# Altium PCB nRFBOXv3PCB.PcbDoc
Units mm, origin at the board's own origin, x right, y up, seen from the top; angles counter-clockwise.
Board outline 47.75 x 87.5 mm, 2 copper layers (Top Layer, Bottom Layer); 76 components, 63 nets, 357 pads, 84 vias.
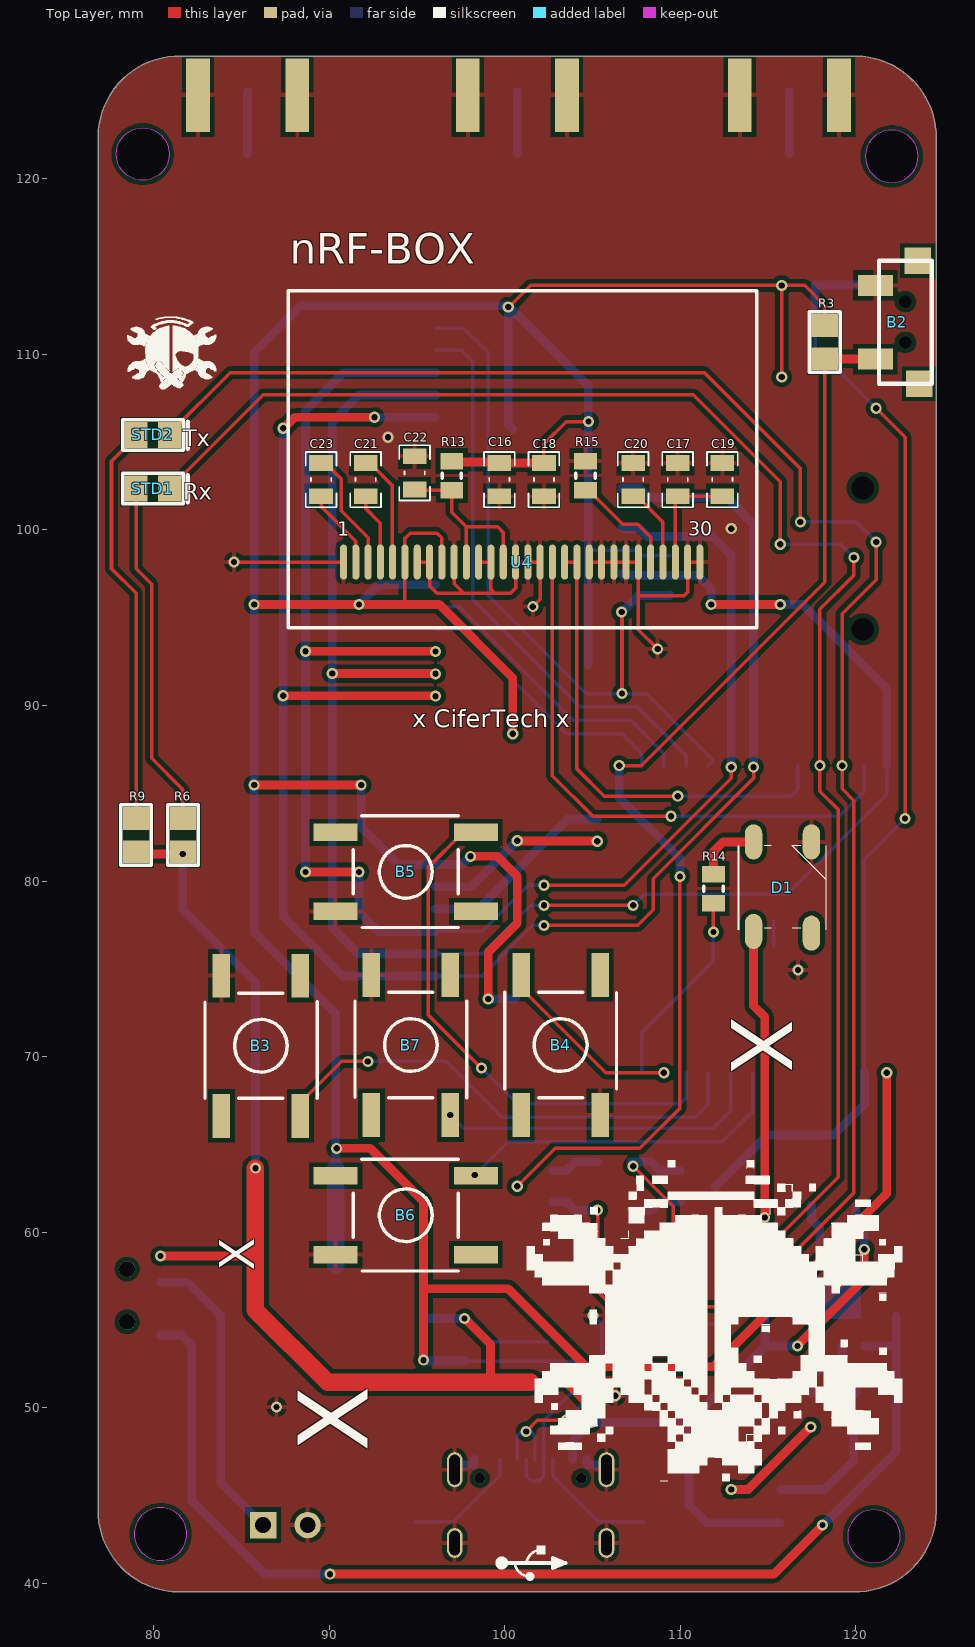
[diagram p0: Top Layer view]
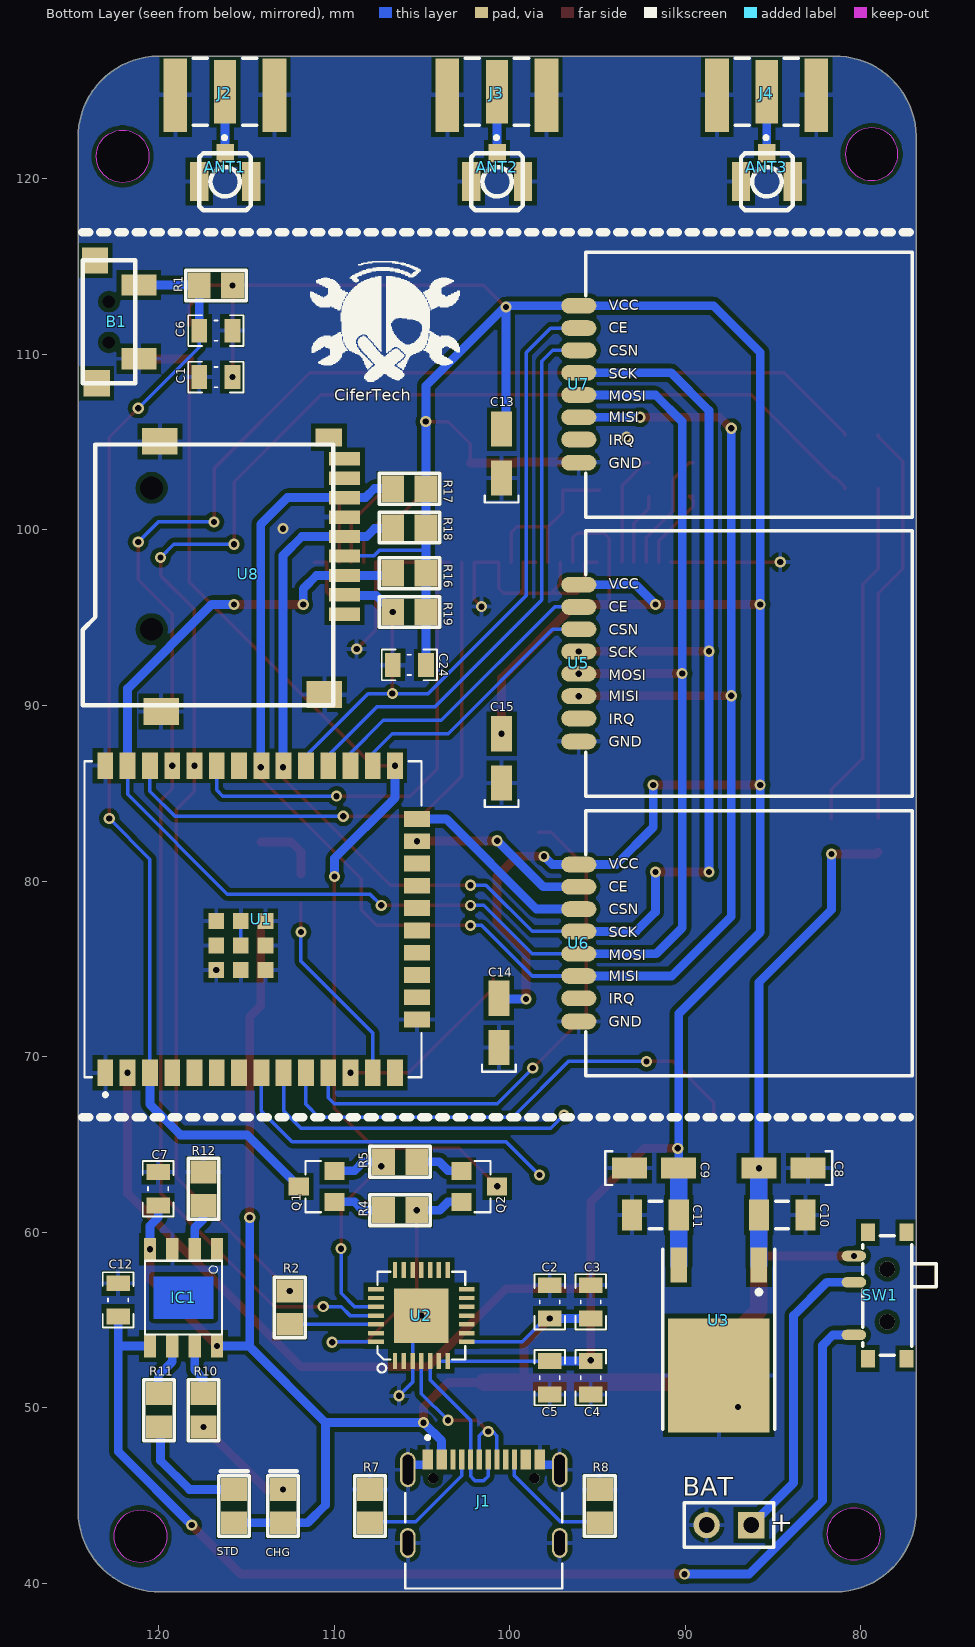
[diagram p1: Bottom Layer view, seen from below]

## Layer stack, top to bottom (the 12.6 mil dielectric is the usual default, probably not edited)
Top Solder: solder mask 0.0102, Solder Resist, Dk 3.5
Top Layer: signal copper 0.0356
Dielectric 1: dielectric 0.32, FR-4, Dk 4.8
Bottom Layer: signal copper 0.0356
Bottom Solder: solder mask 0.0102, Solder Resist, Dk 3.5

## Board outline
76.835,44.196 ccw(c81.47,44.133) 81.407,39.497 119.888,39.497 ccw(c119.951,44.132) 124.587,44.069 124.587,122.301 ccw(c119.952,122.364) 120.015,127 81.534,127 ccw(c81.471,122.365) 76.835,122.428
cut-out: 78.891,42.799 ccw(c80.391,42.799) 80.391,41.299 ccw(c80.391,42.799) 81.891,42.799 ccw(c80.391,42.799) 80.391,44.299 ccw(c80.391,42.799)
cut-out: 119.531,42.672 ccw(c121.031,42.672) 121.031,41.172 ccw(c121.031,42.672) 122.531,42.672 ccw(c121.031,42.672) 121.031,44.172 ccw(c121.031,42.672)
cut-out: 79.375,119.912 cw(c79.375,121.412) 77.875,121.412 cw(c79.375,121.412) 79.375,122.912 cw(c79.375,121.412) 80.875,121.412 cw(c79.375,121.412)
cut-out: 120.547,121.285 ccw(c122.047,121.285) 122.047,119.785 ccw(c122.047,121.285) 123.547,121.285 ccw(c122.047,121.285) 122.047,122.785 ccw(c122.047,121.285)

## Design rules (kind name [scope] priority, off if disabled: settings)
Clearance [All] p1: gap=0.254 ignorepadtopadclearanceinfootprint=FALSE except(0: Arc-Hole Track-Hole SMDPad-Hole THPad-Hole Via-Hole Fill-Hole Poly-Hole Region-Hole Text-Hole)
PolygonConnect [All] p1: connectstyle=Relief reliefconductorwidth=0.254 reliefentries=4 polygonreliefangle="90 Angle" airgapwidth=0.254
RoutingVias [All] p1: holewidth=0.711 width=1.27 viastyle="Through Hole" minholewidth=0.711 minwidth=1.27 maxholewidth=0.711 maxwidth=1.27
SolderMaskExpansion [All] p1: expansion=0.102
Width [All] p1: maxlimit=1 minlimit=0.2 preferedwidth=0.5 minimp=50.000000 maximp=50.000000 favimp=50.000000
30 further rules are at their usual default settings.

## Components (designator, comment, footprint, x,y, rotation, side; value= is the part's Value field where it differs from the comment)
ANT1 "ANT U.FL" "U.FL SMD" 116.205,120.65 r0 bottom
ANT2 "ANT U.FL" "U.FL SMD" 100.711,120.65 r0 bottom
ANT3 "ANT U.FL" "U.FL SMD" 85.344,120.65 r0 bottom
B1 "BUTTON" "PUSH BUTTON SMD" 122.809,111.76 r0 bottom
B2 "BUTTON" "PUSH BUTTON SMD" 122.809,111.926 r0 top
B3 "Button" "PUSH BUTTON 4 PIN SMD 5" 86.106,70.612 r90 top locked
B4 "Button" "PUSH BUTTON 4 PIN SMD 5" 103.187,70.657 r270 top locked
B5 "Button" "PUSH BUTTON 4 PIN SMD 5" 94.361,80.522 r180 top locked
B6 "Button" "PUSH BUTTON 4 PIN SMD 5" 94.361,60.96 r180 top locked
B7 "Button" "PUSH BUTTON 4 PIN SMD 5" 94.647,70.657 r90 top locked
BAT "Battery" Bat 69.342,52.959 r0 bottom
C1 "100nf" CAP0805 116.73,108.712 r180 bottom
C2 "10uf" CAP0805 97.714,56.023 r270 bottom
C3 "100nf" CAP0805 95.377,56.023 r270 bottom
C4 "10uf" CAP0805 95.377,51.705 r90 bottom
C5 "100nf" CAP0805 97.714,51.705 r90 bottom
C6 "100nf" CAP0805 116.73,111.351 r0 bottom
C7 "100nf" CAP0805 120.025,62.468 r270 bottom
C8 "Capacitor Tantalum SMD" "Tan 1206 (3216X18L) Size A" 77.665,69.103 r0 bottom value=2.2uf
C9 "Capacitor Tantalum SMD" "Tan 1206 (3216X18L) Size A" 98.502,58.181 r180 bottom value=2.2uf
C10 "10uf" "CAP 1206 (3216X15L)" 84.474,60.974 r0 bottom
C11 "10uf" "CAP 1206 (3216X15L)" 91.694,60.974 r180 bottom
C12 "100nf" CAP0805 122.301,56.134 r270 bottom
C13 "Capacitor Tantalum SMD" "Tan 1206 (3216X18L) Size A" 94.996,97.615 r90 bottom value=10uf
C14 "Capacitor Tantalum SMD" "Tan 1206 (3216X18L) Size A" 95.154,65.185 r90 bottom value=10uf
C15 "Capacitor Tantalum SMD" "Tan 1206 (3216X18L) Size A" 94.996,80.258 r90 bottom value=10uf
C16 "10uf" CAP0805 99.695,102.87 r270 top
C17 "10uf" CAP0805 109.855,102.87 r270 top
C18 "100nf" CAP0805 102.235,102.87 r270 top
C19 "100nf" CAP0805 112.395,102.87 r270 top
C20 "2.2uf" CAP0805 107.315,102.87 r90 top
C21 "1uf" CAP0805 92.075,102.87 r90 top
C22 "2.2uf" CAP0805 94.869,103.251 r90 top
C23 "1uf" CAP0805 89.535,102.87 r90 top
C24 "100nf" CAP0805 105.711,92.311 r0 bottom
CHG "LED" L0805 112.903,45.339 r90 bottom
D1 "LED RGB WS2812" "LED 5050 WS2812B" 115.824,79.629 r90 top
IC1 "TP4056" SOP-8 118.578,56.266 r270 bottom
J1 "TYPE-C-31-M-12" HRO_TYPE-C-31-M-12 101.473,42.291 r180 bottom
J2 "SMA" SAMTEC_SMA-J-P-H-ST-EM1 116.216,124.968 r0 bottom
J3 "SMA" SAMTEC_SMA-J-P-H-ST-EM1 100.722,124.968 r0 bottom
J4 "SMA" SAMTEC_SMA-J-P-H-ST-EM1 85.355,124.968 r0 bottom
Q1 "S8050" SOT-23 110.998,62.596 r90 bottom
Q2 "S8050" SOT-23 101.727,62.596 r270 bottom
R1 "4.7k" "RES 0805" 117.68,113.931 r270 bottom
R2 "470" "RES 0805" 112.522,56.645 r0 bottom
R3 "4.7k" "RES 0805" 118.237,109.755 r0 top
R4 "12k" "RES 0805" 105.288,61.25 r90 bottom
R5 "12k" "RES 0805" 107.188,64.008 r270 bottom
R6 "1k" "RES 0805" 81.666,81.661 r0 top
R7 "5.1k" "RES 0805" 107.95,43.439 r180 bottom
R8 "5.1k" "RES 0805" 94.869,43.439 r180 bottom
R9 "1k" "RES 0805" 78.999,81.666 r0 top
R10 "1k" "RES 0805" 117.435,50.8 r0 bottom
R11 "1k" "RES 0805" 119.975,50.8 r0 bottom
R12 "1k" "RES 0805" 117.435,61.518 r180 bottom
R13 "10k" "RES 0805 (2012X06L)" 96.982,102.268 r90 top
R14 "1k" "RES 0805 (2012X06L)" 111.887,78.741 r90 top
R15 "390k" "RES 0805 (2012X06L)" 104.602,102.268 r90 top
R16 "10K" "RES 0805" 106.661,97.536 r270 bottom
R17 "10K" "RES 0805" 106.661,102.349 r270 bottom
R18 "10K" "RES 0805" 106.661,100.133 r270 bottom
R19 "10K" "RES 0805" 106.661,95.32 r270 bottom
STD "LED" L0805 115.697,45.339 r90 bottom
STD1 "LED" L0805 80.899,102.362 r0 top
STD2 "LED" L0805 80.899,105.41 r0 top
SW1 "SlideSwitch" SWSLIDT_SPDT_MSS3 78.486,56.388 r270 bottom
U1 "ESP32-WROOM-32U" XCVR_ESP32-WROOM-32U 114.623,77.824 r90 bottom
U2 "CP2102" QFN28G_0.5-5X5MM 105.029,55.245 r90 bottom
U3 "LF33" D-PACK 85.799,58.13 r0 bottom
U4 "OLED_0.96IN_WHITE" OLED_0.96IN_WHITE_SSD1306 100.965,98.171 r0 top locked
U5 "NRF24L01" NRF24L01_GT24MINI_MS 86.36,92.443 r180 bottom
U6 "NRF24L01" NRF24L01_GT24MINI_MS 86.36,76.499 r180 bottom
U7 "NRF24L01" NRF24L01_GT24MINI_MS 86.36,108.331 r180 bottom
U8 "SD CARD SPI MODE" "MICRO SD" 110.046,104.868 r270 bottom
? "Comment" "LOGO USB1" 101.473,41.148 r0 top

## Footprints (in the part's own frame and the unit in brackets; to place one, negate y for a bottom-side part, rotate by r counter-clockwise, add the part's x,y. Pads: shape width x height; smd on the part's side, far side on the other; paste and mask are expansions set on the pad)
Bat [mm]
  rect 1.5x1.5 hole 0.9: 1(16.891,9.652)
  round 1.5 hole 0.9: 2(19.431,9.652)
  silkscreen extent 15.62,8.38 20.7,10.92
CAP0805 [mm] "Chip Capacitor, 2-Leads, Body 2/00x1/25mm, IPC Medium Density DESIGNER:ABBAS BASEREH"
  rect 0.9x1.35 smd: 1(-0.95,0) 2(0.95,0)
  silkscreen extent -1.58,-0.87 1.58,0.87, body extent -1.02,-0.65 1.02,0.65, height 0.5
"CAP 1206 (3216X15L)" [mm] "Chip Capacitor, 2-Leads, Body 3.2x1.6mm, IPC High Density"
  rect 1.15x1.75 smd: 1(-1.325,0) 2(1.325,0)
  silkscreen extent -0.35,-0.77 0.35,0.77, body extent -1.6,-0.8 1.6,0.8, height 1
D-PACK [mm] "D-PACK"
  rect 0.95x2 smd: 1(0,0) 3(4.57,0)
  rect 5.8x6.5 smd: 2(2.285,6.3)
  silkscreen extent -0.91,-0.9 5.49,9.35, body extent -1.03,-0.45 5.55,9.25, height 2.3
HRO_TYPE-C-31-M-12 [mm]
  rect 0.6x1.14 smd mask+0.05: A1_B12(-3.2,4.75) A4_B9(-2.4,4.75) B1_A12(3.2,4.75) B4_A9(2.4,4.75)
  rect 0.3x1.14 smd mask+0.05: A5(-1.25,4.75) A6(-0.25,4.75) A7(0.25,4.75) A8(1.25,4.75) B5(1.75,4.75) B6(0.75,4.75) B7(-0.75,4.75) B8(-1.75,4.75)
  oval 0.9x2 hole 0.6 slot 1.7 at 90 deg: S1(-4.325,4.17) S2(4.325,4.17)
  oval 0.9x1.7 hole 0.6 slot 1.4 at 90 deg: S3(-4.325,0) S4(4.325,0)
  round 0.6 hole 0.6 unplated: ""(-2.89,3.68) ""(2.89,3.68)
  silkscreen extent -4.47,-2.6 4.47,6.1, body extent -4.47,-2.6 4.47,5.3, height 3.31
L0805 [mm] "Body 2.0x1.3mm, IPC High Density"
  rect 1.3x1.5 smd: A(-1.9,0) K(0,0)
  silkscreen extent -2.68,-0.87 1.03,0.87, body extent -1.95,-0.63 0.05,0.62, height 0.68
"LED 5050 WS2812B" [mm]
  oval 2x1 smd: 1(-2.5,1.65) 2(-2.6,-1.65) 3(2.6,-1.65) 4(2.6,1.65)
  silkscreen extent -2.41,-2.49 2.4,2.51, body extent -2.74,-2.49 2.66,2.51, height 1.6
"LOGO USB1" [mm] "General USB Logo"
  silkscreen extent -1.82,-0.89 2.01,0.99
"MICRO SD" [mil] "MICRO SD"
  rect 30x70 smd: 1(380.91,25.07) 2(337.29,25.07) 3(293.66,25.07) 4(250.04,25.07) 5(206.41,25.07) 6(162.79,25.07) 7(119.16,25.07) 8(75.54,25.07) 9(31.91,25.07)
  rect 60x80 smd: 6(-7.09,-388.93) 6(560.91,-19.93) 6(598.91,-385.93)
  rect 40x60 smd: 10(-16.09,-9.93)
  round 0 hole 51.18: ""(97.44,-407.48) ""(414.37,-407.48)
  silkscreen extent 0,-562 585,0, body extent -25,-565 609,26, height 73
NRF24L01_GT24MINI_MS [mm] "2.4GHz Transceiver MODULE, SMD"
  oval 2x0.9 smd mask+0.1: 1(-9.7,4.44) 2(-9.7,3.17) 3(-9.7,1.9) 4(-9.7,0.63) 5(-9.7,-0.64) 6(-9.7,-1.91) 7(-9.7,-3.18) 8(-9.7,-4.5)
  silkscreen extent -9.3,-7.6 9.3,7.5, body extent -9.2,-7.5 9.2,7.4, height 2.25
OLED_0.96IN_WHITE_SSD1306 [mm] "OLED, 0.96IN, Monochrome white, SSD1306"
  oval 0.4x2 smd: 1(-10.15,0) 2(-9.45,0) 3(-8.75,0) 4(-8.05,0) 5(-7.35,0) 6(-6.65,0) 7(-5.95,0) 8(-5.25,0) 9(-4.55,0) 10(-3.85,0) 11(-3.15,0) 12(-2.45,0) 13(-1.75,0) 14(-1.05,0) 15(-0.35,0) 16(0.35,0) 17(1.05,0) 18(1.75,0) 19(2.45,0) 20(3.15,0) 21(3.85,0) 22(4.55,0) 23(5.25,0) 24(5.95,0) 25(6.65,0) 26(7.35,0) 27(8.05,0) 28(8.75,0) 29(9.45,0) 30(10.15,0)
  silkscreen extent -13.3,-3.75 13.4,15.45, body extent -13.35,-6.82 13.35,15.4, height 3.82
"PUSH BUTTON 4 PIN SMD 5" [mm]
  rect 2.5x1 smd: 1(-3.992,2.25) 2(-3.992,-2.25) 3(3.992,-2.25) 4(3.992,2.25)
  silkscreen extent -3,-3.2 3,3.17, body extent -4.5,-3 4.5,3, height 5
"PUSH BUTTON SMD" [mm]
  rect 1.5x1.5 smd: 1(0.712,3.405) 4(0.812,-3.595)
  rect 2x1.2 smd: 2(-1.688,2.005) 3(-1.688,-2.195)
  round 0 hole 0.7: ""(0.012,-1.245) ""(0.02,1.079)
  silkscreen extent -1.49,-3.59 1.51,3.41
QFN28G_0.5-5X5MM [mm]
  rect 0.9x0.254 smd: 1(-2.59,1.5) 2(-2.59,1) 3(-2.59,0.5) 4(-2.59,0) 5(-2.59,-0.5) 6(-2.59,-1) 7(-2.59,-1.5) 15(2.59,-1.5) 16(2.59,-1) 17(2.59,-0.5) 18(2.59,0) 19(2.59,0.5) 20(2.59,1) 21(2.59,1.5)
  rect 0.254x0.9 smd: 8(-1.5,-2.59) 9(-1,-2.59) 10(-0.5,-2.59) 11(0,-2.59) 12(0.5,-2.59) 13(1,-2.59) 14(1.5,-2.59) 22(1.5,2.59) 23(1,2.59) 24(0.5,2.59) 25(0,2.59) 26(-0.5,2.59) 27(-1,2.59) 28(-1.5,2.59)
  rect 3.1x3.1 smd paste-3: 29(0,0)
  silkscreen extent -3.25,-2.5 2.5,2.5
"RES 0805" [mm] "RES 0805"
  rect 1.5x1.3 smd: 1(0,0) 2(0,1.9)
  silkscreen extent -0.87,-0.77 0.87,2.68, body extent -0.63,-0.07 0.64,1.97, height 0.6
"RES 0805 (2012X06L)" [mm] "Chip Resistor, 2-Leads, Body 2.0x1.3mm, IPC High Density _ (0.100 W)"
  rect 0.95x1.3 smd: 1(0,0) 2(1.65,0)
  silkscreen extent 0.67,-0.55 0.97,0.55, body extent -0.19,-0.63 1.84,0.64, height 0.6
SAMTEC_SMA-J-P-H-ST-EM1 [mm]
  rect 1.27x3.6 smd: 1(0,0)
  rect 1.35x4.2 smd: 2_1(-2.825,0.2) 3_1(2.825,0.2)
  rect 1.35x4.2 smd far side: 2_2(-2.825,0.2) 3_2(2.825,0.2)
  silkscreen extent -1.8,-1.9 1.8,2.72, body extent -3.17,-11.42 3.18,1.91, height 3.55
SOP-8 [mm]
  rect 1.3x0.7 smd: 1(-2.75,1.905) 2(-2.75,0.635) 3(-2.75,-0.635) 4(-2.75,-1.905) 5(2.75,-1.905) 6(2.75,-0.635) 7(2.75,0.635) 8(2.75,1.905)
  Top Layer region: 1.2,-1.7 -1.2,-1.7 -1.2,1.7 1.2,1.7
  silkscreen extent -2.1,-2.2 2.1,2.2
SOT-23 [mil]
  rect 40x45 smd: 1(-35,-40) 2(35,-40) 3(0,40)
  silkscreen extent -58,-10 58,25, body extent -57,-51 57,51, height 55
SWSLIDT_SPDT_MSS3 [mm] "Switch, Slide, SPDT,"
  oval 0.6x1.4 smd: 1(2.25,-1.9) 2(-0.75,-1.9) 3(-2.25,-1.9)
  rect 1x0.8 smd: EP(-3.6,-1.1) EP(-3.6,1.1) EP(3.6,-1.1) EP(3.6,1.1)
  round 0.9 hole 0.9 unplated: ""(-1.5,0) ""(1.5,0)
  silkscreen extent -3.4,-1.4 3.4,2.8, body extent -3.85,-2.24 3.85,2.76, height 1.4
"Tan 1206 (3216X18L) Size A" [mil]
  rect 78.7x47.2 smd: 1(210,215) 2(320.22,215)
  silkscreen extent 156,177 171,253, body extent 193,179 336,250, height 71
"U.FL SMD" [mm] "U.FL Antenna-Design:Ali Hafizi"
  rect 1x1.05 smd: 1(0.002,-0.8)
  rect 1.05x2.2 smd: 2(-1.475,0.8) 2(1.475,0.8)
  silkscreen extent -1.47,-0.8 1.47,2.44, body extent -1.73,-0.76 1.67,2.34, height 1.25
XCVR_ESP32-WROOM-32U [mm]
  rect 1.5x0.9 smd: 1(-8.75,8.41) 2(-8.75,7.14) 3(-8.75,5.87) 4(-8.75,4.6) 5(-8.75,3.33) 6(-8.75,2.06) 7(-8.75,0.79) 8(-8.75,-0.48) 9(-8.75,-1.75) 10(-8.75,-3.02) 11(-8.75,-4.29) 12(-8.75,-5.56) 13(-8.75,-6.83) 14(-8.75,-8.1) 25(8.75,-8.1) 26(8.75,-6.83) 27(8.75,-5.56) 28(8.75,-4.29) 29(8.75,-3.02) 30(8.75,-1.75) 31(8.75,-0.48) 32(8.75,0.79) 33(8.75,2.06) 34(8.75,3.33) 35(8.75,4.6) 36(8.75,5.87) 37(8.75,7.14) 38(8.75,8.41)
  rect 0.9x1.5 smd: 15(-5.715,-9.35) 16(-4.445,-9.35) 17(-3.175,-9.35) 18(-1.905,-9.35) 19(-0.635,-9.35) 20(0.635,-9.35) 21(1.905,-9.35) 22(3.175,-9.35) 23(4.445,-9.35) 24(5.715,-9.35)
  rect 0.9x0.9 smd: 39_1(-2.9,2.09) 39_2(-1.5,2.09) 39_3(-0.1,2.09) 39_4(-2.9,0.69) 39_5(-1.5,0.69) 39_6(-0.1,0.69) 39_7(-2.9,-0.71) 39_8(-1.5,-0.71) 39_9(-0.1,-0.71)
  round 0 all layers, no hole mask+0: 40_1(-2.2,2.09) 40_2(-0.8,2.09) 40_3(-2.9,1.39) 40_4(-1.5,1.39) 40_5(-0.1,1.39) 40_6(-2.2,0.69) 40_7(-0.8,0.69) 40_8(-2.9,-0.01) 40_9(-1.5,-0.01) 40_10(-0.1,-0.01) 40_11(-2.2,-0.71) 40_12(-0.8,-0.71)
  silkscreen extent -10.1,-9.6 9,9.6, body extent -9,-9.6 9,9.6, height 3.35

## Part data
ANT1 ANT2 ANT3: "Antenna"
B1 B2: library part "PUSH BUTTON RIGHT", "PUSH BUTTON"
B3 B4 B5 B6 B7: library part "PUSH BUTTON 4 PIN", "PUSH BUTTON"
C1 C2 C3 C4 C5 C6 C7 C10 C11 C12 C16 C17 C18 C19 C20 C21 C22 C23 C24: library part "CAP SMD", "Capacitor"
D1: "LED"
IC1: "Complete single cell Li-Ion battery with a constant current / constant voltage linear charger", Package="Package Analog Devices"
J1: "USB Connectors 24 Receptacle 1 8.94*7.3mm RoHS", Package=Package
J2 J3 J4: library part SMA-J-P-H-ST-EM1, "SMA Connector Jack, Female Socket 50Ohm Board Edge, End Launch Solder", Package=None
Q1 Q2: library part SMD-TRANSISTORS-NPN-25V-500MW(SOT-23), "Bipolar (BJT) Transistor NPN 25 V 500 mA 150MHz 300 mW Surface Mount SOT-23", Package=None
R1 R2 R3 R4 R5 R6 R7 R8 R9 R10 R11 R12 R13 R14 R15 R16 R17 R18 R19: library part RES, "RESISTOR"
SW1: library part SWSLIDT_SPDT_MSS3, "SWITCH, SLIDE, SPDT, SMD"
U1: "Bluetooth, WiFi 802.11b/g/n, Bluetooth v4.2 +EDR, Class 1, 2 and 3 Transceiver Module 2.4GHz ~ 2.5GHz Antenna Not Included, U.FL Surface Mount", Package="NON STANDARD-39 Espressif"
U2: library part INTERFACE-CP2102-GMR(QFN28), "USB Bridge, USB to UART USB 2.0 UART Interface 28-QFN _5x5_", Package="VFQFN-28 Vishay Siliconix"
U3: "3.3V VOLTAGE REGULATOR"
U4: library part OLED_0.96IN_WHITE_SSD1306, "OLED, 0.96\", Monochrome white, SSD1306"
U5 U6 U7: library part NRF24L01_GT24MINI_MS, "2.4GHz Transceiver MODULE, SMD"

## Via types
v1: diameter 0.635, hole 0.356, Top Layer to Bottom Layer, 84 vias

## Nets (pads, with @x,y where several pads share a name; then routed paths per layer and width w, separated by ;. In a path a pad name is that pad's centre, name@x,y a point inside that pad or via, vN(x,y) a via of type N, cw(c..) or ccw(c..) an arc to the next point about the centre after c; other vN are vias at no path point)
3v3: C1.2 C4.2 C5.2 C9.2 C11.2 C13.2 C14.2 C15.2 C16.1 C18.1 C24.1 R1.2 R3.2 R13.2 R16.2 R17.2 R18.2 R19.2 U1.2 U2.6 U2.7 U3.3 U4.6 U4.9 U5.1 U6.1 U7.1 U8.4 | length 261.8
  Top Layer w0.2: 94.315,95.758 U4.6 94.315,99.522 94.615,99.822 96.139,99.822 96.415,99.546 U4.9 ; v1(100.203,112.709) 100.265,112.709 101.487,113.931 v1(115.78,113.931) ; C18.1 102.235,104.902 103.505,106.172 v1(104.775,106.172) ; v1(115.78,108.712) v1(115.78,113.931) ; R3.2 118.237,112.776 117.082,113.931 v1(115.78,113.931)
  Top Layer w0.5: v1(85.725,85.471) v1(91.821,85.471) ; v1(85.725,95.758) v1(91.694,95.758) 94.315,95.758 96.266,95.758 100.457,91.567 v1(100.457,88.392) ; v1(90.424,64.77) 92.329,64.77 95.377,61.722 95.377,56.769 ; v1(95.377,52.705) 95.377,56.769 ; R13.2 97.031,103.869 99.646,103.869 C16.1 C18.1 ; v1(98.044,81.407) 99.568,81.407 100.711,80.264 100.711,77.597 99.06,75.946 v1(99.06,73.279) ; v1(121.763,69.074) 121.763,62.2 111.887,52.324 104.648,52.324 100.203,56.769 95.377,56.769
  Bottom Layer w0.2: C5.2 U2.7 U2.6 ; 104.761,98.835 107.413,98.835 107.731,98.517 U8.4
  Bottom Layer w0.5: C9.2 90.369,72.445 85.725,77.089 v1(85.725,85.471) v1(85.725,95.758) 85.725,110.109 88.387,112.771 U7.1 v1@100.203,112.771 ; v1(91.694,95.758) 92.819,96.883 U5.1 ; v1(91.821,85.471) 91.821,83.058 93.94,80.939 U6.1 97.576,80.939 v1(98.044,81.407) ; C4.2 C5.2 ; v1(99.06,73.279) 100.575,73.279 C14.2 ; C13.2 100.203,106.003 v1(100.203,112.709) v1@100.203,112.771 ; C24.1 104.761,95.32 R16.2 104.761,98.835 R18.2 R17.2 104.761,108.218 100.208,112.771 v1@100.203,112.771
  Bottom Layer w1: U3.3 C11.2 C9.2
+5v: C2.2 C3.2 C7.2 C8.2 C10.2 CHG.A D1.1 IC1.4 IC1.8 J1.A4_B9 R6.1 R9.1 STD.A SW1.3 U2.8 U3.1 | length 135.6
  Top Layer w0.5: R9.1 79.131,81.534 v1(81.661,81.534) ; v1(80.386,58.638) 85.763,58.638 85.798,58.674 ; v1(97.714,55.073) 99.187,53.6 99.187,51.435 ; 101.473,51.435 103.505,51.435 104.902,50.038 v1(104.902,49.144) ; D1.1 114.174,72.897 114.808,72.263 v1(114.808,60.833) ; v1(116.673,53.516) 120.483,57.326 v1(120.483,59.016)
  Top Layer w1: v1(85.798,63.642) 85.798,58.674 85.798,55.553 89.916,51.435 99.187,51.435 101.473,51.435
  Bottom Layer w0.2: v1(97.714,55.073) 97.962,55.073 99.29,53.745 U2.8
  Bottom Layer w0.5: v1(81.661,81.534) 81.661,78.359 85.798,74.222 v1(85.798,63.642) ; C3.2 v1(97.714,55.073) ; J1.A4_B9 103.873,48.115 v1(104.902,49.144) 110.49,49.144 ; v1(114.808,60.833) 114.808,53.57 114.862,53.516 ; STD.A CHG.A 111.501,43.439 110.49,44.45 110.49,49.144 ; v1(116.673,53.516) 114.862,53.516 ; C7.2 120.015,61.508 120.015,60.833 120.483,60.365 v1(120.483,59.016) ; 110.49,49.144 114.862,53.516
  Bottom Layer w1: U3.1 C10.2 v1(85.798,63.642)
ACTIVE: U2.11
BAT: C12.2 IC1.5 SW1.1 | length 65.1
  Top Layer w0.5: v1(90.043,40.513) 115.316,40.513 v1(118.11,43.307)
  Bottom Layer w0.5: SW1.1 81.586,54.138 82.169,53.555 82.169,44.704 86.36,40.513 v1(90.043,40.513) ; v1(118.11,43.307) 122.301,47.498 122.301,53.516 ; IC1.5 122.301,53.516 ; C12.2 122.301,53.516
CC1: J1.A5 R7.1 | length 7.3
  Bottom Layer w0.2: J1.A5 102.723,46.117 105.345,43.495 107.894,43.495 R7.1
CC2: J1.B5 R8.1 | length 6.9
  Bottom Layer w0.2: R8.1 94.925,43.495 97.101,43.495 99.723,46.117 J1.B5
CLK: R18.1 U1.30 U5.4 U6.4 U7.4 U8.5 | length 92.2
  Top Layer w0.2: v1(102.235,79.756) 106.807,79.756 112.903,85.852 v1(112.903,86.487)
  Top Layer w0.5: v1(88.646,80.518) v1(91.694,80.518) ; v1(88.646,93.091) 96.042,93.091 v1(96.06,93.073)
  Bottom Layer w0.2: U6.4 98.719,77.129 101.346,79.756 v1(102.235,79.756)
  Bottom Layer w0.5: v1(88.646,80.518) v1(88.646,93.091) 88.646,106.807 90.8,108.961 U7.4 ; v1(91.694,80.518) 91.694,78.232 92.797,77.129 U6.4 ; R18.1 106.718,100.076 107.696,100.076 108.147,99.625 U8.5 111.83,99.625 112.903,98.552 v1(112.903,86.487)
CS: R19.1 U1.29 U7.2 U8.2 | length 42.3
  Top Layer w0.2: v1(106.661,95.32) 106.68,95.301 v1(106.68,90.678)
  Bottom Layer w0.2: U7.2 97.668,111.501 99.06,110.109 99.06,96.266 104.648,90.678 v1(106.68,90.678) 108.067,90.678 111.887,86.858 U1.29
  Bottom Layer w0.5: v1(106.661,95.32) 107.607,96.266 109.374,96.266 U8.2
CTS: U2.23
D+: J1.A6 J1.B6 U2.4 | length 10.5
  Top Layer w0.2: v1(101.219,48.641) 101.854,49.276 v1(103.505,49.276)
  Bottom Layer w0.2: J1.B6 100.723,48.399 100.965,48.641 v1(101.219,48.641) 101.473,48.641 101.723,48.391 J1.A6 ; v1(103.505,49.276) 105.029,50.8 U2.4
D-: J1.A7 J1.B7 U2.5 | length 9.7
  Bottom Layer w0.2: J1.A7 101.223,46.097 101.473,45.847 101.981,45.847 102.223,46.089 102.223,47.762 102.223,49.264 104.529,51.57 U2.5
DCD: U2.1
DSR: U2.27
DTR: Q2.2 R4.1 U2.28 | length 15.9
  Top Layer w0.2: v1(105.288,61.25) 105.288,56.637 108.204,53.721 v1(110.109,53.721)
  Bottom Layer w0.2: U2.28 110.085,53.745 v1(110.109,53.721)
  Bottom Layer w0.5: Q2.2 102.758,61.722 103.505,61.722 103.977,61.25 v1(105.288,61.25)
GND: ANT1.2 ANT2.2 ANT3.2 B1.2 B2.2 B3.4 B4.4 B5.4 B6.4 B7.4 BAT.2 C1.1 C2.1 C3.1 C4.1 C5.1 C6.1 C7.1 C8.1 C9.1 C10.1 C11.1 C12.1 C13.1 C14.1 C15.1 C16.2 C17.1 C18.2 C19.1 C20.2 C22.2 C24.2 D1.3 IC1.3 J1.A1_B12 J1.B1_A12 J1.S1 J1.S2 J1.S3 J1.S4 J2.2_1 J2.2_2 J2.3_1 J2.3_2 J3.2_1 J3.2_2 J3.3_1 J3.3_2 J4.2_1 J4.2_2 J4.3_1 J4.3_2 R7.2 R8.2 R12.2 R15.2 U1.1 U1.15 U1.38 U1.39_1 U1.39_2 U1.39_3 U1.39_4 U1.39_5 U1.39_6 U1.39_7 U1.39_8 U1.39_9 U2.3 U2.29 U3.2 U4.1 U4.7 U4.8 U4.10 U4.12 U4.13 U4.15 U4.16 U4.17 U4.21 U4.22 U4.23 U4.24 U4.25 U4.29 U4.30 U5.8 U6.8 U7.8 U8.6 | length 46.8
  Top Layer w0.2: v1(84.582,98.171) U4.1 ; U4.7 U4.8 95.715,96.817 96.139,96.393 97.663,96.393 ; U4.10 97.115,96.941 97.663,96.393 ; U4.12 U4.13 99.215,96.619 99.441,96.393 ; v1(101.6,95.631) 102.015,96.046 U4.17 U4.16 U4.15 100.615,96.678 100.33,96.393 99.441,96.393 ; U4.21 U4.22 U4.23 U4.24 U4.25 107.615,96.243 ; v1(108.712,93.218) 107.615,94.315 107.615,96.243 ; U4.30 U4.29 110.415,96.445 110.213,96.243 107.615,96.243 ; 97.663,96.393 99.441,96.393
  Bottom Layer w0.2: v1(105.029,55.245) 105.529,54.745 U2.3 105.529,51.443 v1(106.299,50.673) ; U1.39_5 U1.39_6
  Bottom Layer w0.5: J1.S2 97.148,46.566 97.333,46.751 98.223,46.751 98.269,46.797 J1.B1_A12@98.269,47.041 ; J1.A1_B12@104.677,47.041 104.677,46.797 104.723,46.751 105.613,46.751 105.798,46.566 J1.S1
  other v1: 86.995,50.038 116.713,74.924 112.903,100.076 93.345,105.283
GPIO0: B2.3 Q2.3 R3.1 U1.25 | length 63.7
  Top Layer w0.2: v1(100.711,62.611) 102.87,64.77 107.696,64.77 109.982,67.056 v1(109.982,80.264) ; v1(106.523,86.574) 107.783,86.574 118.237,97.028 R3.1
  Top Layer w0.5: R3.1 118.249,109.743 121.109,109.743 B2.3
  Bottom Layer w0.5: v1(106.523,86.574) 106.523,84.739 109.982,81.28 v1(109.982,80.264)
IO2: U1.24 U6.3 | length 11.3
  Bottom Layer w0.5: U6.3 98.465,78.399 103.605,83.539 U1.24
IO4: U1.26 U5.3 | length 15.4
  Bottom Layer w0.2: U5.3 97.554,94.343 103.505,88.392 106.68,88.392 107.793,87.279 U1.26
IO12: U1.14
IO13: U1.16
IO14: R14.1 U1.13 | length 11.4
  Top Layer w0.2: v1(111.887,77.089) R14.1
  Bottom Layer w0.2: U1.13 107.793,71.344 111.887,75.438 v1(111.887,77.089)
IO15: U1.23 U6.2 | length 10.3
  Top Layer w0.5: v1(100.711,82.296) 100.725,82.282 105.259,82.282 v1(105.273,82.269)
  Bottom Layer w0.5: U6.2 98.084,79.669 v1(100.711,82.296)
IO16: U1.27 U5.2 | length 17.2
  Bottom Layer w0.2: U5.2 97.427,95.613 103.886,89.154 107.188,89.154 109.063,87.279 U1.27
IO17: U1.28 U7.3 | length 32.4
  Bottom Layer w0.2: U7.3 97.541,110.231 98.171,109.601 98.171,96.012 104.267,89.916 107.569,89.916 110.333,87.152 U1.28
IO19: R17.1 U1.31 U5.6 U6.6 U7.6 U8.7 | length 102.2
  Top Layer w0.2: v1(102.235,77.47) 107.569,77.47 108.458,78.359 108.458,80.137 114.173,85.852 v1(114.173,86.487)
  Top Layer w0.5: v1(87.376,90.551) 96.042,90.551 v1(96.06,90.533) ; v1(87.376,105.791) 87.413,105.791 88.043,106.421 v1(92.578,106.421)
  Bottom Layer w0.2: U6.6 98.719,74.589 101.6,77.47 v1(102.235,77.47)
  Bottom Layer w0.5: v1(87.376,105.791) v1(87.376,90.551) 87.376,77.978 90.765,74.589 U6.6 ; v1(92.578,106.421) U7.6 ; R17.1 106.674,102.362 107.696,102.362 108.204,101.854 112.649,101.854 114.173,100.33 v1(114.173,86.487)
IO21: U1.33 U4.19 U4.20 | length 27.2
  Top Layer w0.2: U4.19 U4.20 104.115,86.385 105.664,84.836 v1(109.855,84.836)
  Bottom Layer w0.2: v1(109.855,84.836) 116.332,84.836 116.683,85.187 U1.33
IO22: U1.36 U4.18 | length 32.9
  Top Layer w0.2: U4.18 102.715,86.007 105.029,83.693 v1(109.474,83.693)
  Bottom Layer w0.2: v1(109.474,83.693) 119.066,83.693 120.493,85.12 U1.36
IO23: R16.1 U1.37 U5.5 U6.5 U7.5 U8.3 | length 101.6
  Top Layer w0.2: v1(102.235,78.613) v1(107.315,78.613)
  Top Layer w0.5: v1(90.17,91.821) 96.042,91.821 v1(96.06,91.803) ; v1(111.76,95.758) v1(115.697,95.758)
  Bottom Layer w0.2: U6.5 98.719,75.859 101.473,78.613 v1(102.235,78.613) ; v1(107.315,78.613) 107.95,79.248 116.078,79.248 121.763,84.933 U1.37
  Bottom Layer w0.5: U6.5 91.654,75.859 90.17,77.343 v1(90.17,91.821) 90.17,106.172 91.689,107.691 U7.5 ; R16.1 106.788,97.409 U8.3 110.998,97.409 111.76,96.647 v1(111.76,95.758) ; v1(115.697,95.758) 116.967,95.758 121.763,90.962 U1.37
IO25: B3.2 U1.10 | length 28.4
  Top Layer w0.2: B3.2 88.356,67.369 90.709,69.723 v1(92.202,69.723)
  Bottom Layer w0.2: v1(92.202,69.723) 96.647,69.723 99.822,66.548 110.871,66.548 111.603,67.28 U1.10
IO26: B5.2 U1.11 | length 30.3
  Top Layer w0.2: B5.2 97.631,82.772 95.631,80.772 95.631,72.39 v1(98.679,69.342)
  Bottom Layer w0.2: v1(98.679,69.342) 100.711,67.31 109.982,67.31 110.333,67.661 U1.11
IO27: B4.2 U1.12 | length 10.9
  Top Layer w0.2: B4.2 100.937,73.899 105.762,69.074 v1(109.063,69.074)
IO32: B6.2 U1.8 | length 19.5
  Bottom Layer w0.2: v1(98.298,63.246) 100.203,65.151 112.395,65.151 114.143,66.899 U1.8
IO33: B7.2 U1.9 | length 18.9
  Bottom Layer w0.2: v1(96.901,66.675) 97.663,65.913 111.887,65.913 112.873,66.899 U1.9
IO34: U1.6
IO35: U1.7
NetANT1_1: ANT1.1 J2.1 | length 3.5
  Bottom Layer w0.5: ANT1.1 116.211,121.455 116.211,124.963 J2.1
NetANT2_1: ANT2.1 J3.1 | length 3.5
  Bottom Layer w0.5: ANT2.1 100.717,121.455 100.717,124.963 J3.1
NetANT3_1: ANT3.1 J4.1 | length 3.5
  Bottom Layer w0.5: ANT3.1 85.35,121.455 85.35,124.963 J4.1
NetBAT_1: BAT.1 SW1.2 | length 17.2
  Bottom Layer w0.5: SW1.2 81.927,57.138 83.82,55.245 83.82,45.72 BAT.1
NetC17_2: C17.2 C19.2 U4.28 | length 6.3
  Top Layer w0.2: U4.28 109.715,101.78 C17.2 C19.2
NetC20_1: C20.1 U4.27 | length 4.6
  Top Layer w0.2: C20.1 107.54,101.92 109.015,100.445 U4.27
NetC21_1: C21.1 U4.4 | length 4.1
  Top Layer w0.2: C21.1 92.075,101.219 92.915,100.379 U4.4
NetC21_2: C21.2 U4.5 | length 6.4
  Top Layer w0.2: C21.2 92.3,103.82 93.586,102.534 93.586,98.2 U4.5
NetC22_1: C22.1 R13.1 U4.11 U4.14 | length 10.5
  Top Layer w0.2: C22.1 94.902,102.268 R13.1 96.982,101.011 97.815,100.178 ; U4.11 97.815,100.178 ; U4.14 99.915,99.856 99.593,100.178 97.815,100.178
NetC23_1: C23.1 U4.2 | length 4.9
  Top Layer w0.2: C23.1 89.76,101.92 89.535,101.695 89.535,101.346 91.515,99.366 U4.2
NetC23_2: C23.2 U4.3 | length 6.9
  Top Layer w0.2: C23.2 89.76,103.82 90.678,102.902 90.678,101.092 92.215,99.555 U4.3
NetCHG_K: CHG.K R10.2 | length 6
  Top Layer w0.5: v1(112.903,45.339) 113.874,45.339 v1(117.435,48.9)
NetD1_4: D1.4 R14.2 | length 3.8
  Top Layer w0.5: R14.2 111.887,81.661 112.455,82.229 D1.4
NetIC1_2: IC1.2 R12.1 | length 2.7
  Bottom Layer w0.5: R12.1 117.475,61.478 117.475,60.706 117.943,60.238 IC1.2
NetIC1_6: IC1.6 R11.1 | length 3.1
  Bottom Layer w0.5: IC1.6 119.213,52.618 120.015,51.816 120.015,50.84 R11.1
NetIC1_7: IC1.7 R10.1 | length 2.9
  Bottom Layer w0.5: R10.1 117.475,50.84 117.475,51.689 117.943,52.157 IC1.7
NetQ1_1: Q1.1 R4.2 | length 3
  Bottom Layer w0.5: R4.2 108.367,61.25 108.839,61.722 109.967,61.722 Q1.1
NetQ2_1: Q2.1 R5.2 | length 2.8
  Bottom Layer w0.5: Q2.1 102.758,63.5 103.505,63.5 104.013,64.008 R5.2
NetR2_2: R2.2 U2.26 | length 4.9
  Bottom Layer w0.2: U2.26 R2.2
NetR6_2: R6.2 STD1.A | length 19.9
  Top Layer w0.2: STD1.A 78.999,97.785 79.883,96.901 79.883,86.995 81.666,85.212 R6.2
NetR9_2: R9.2 STD2.A | length 23
  Top Layer w0.2: R9.2 78.999,96.388 77.597,97.79 77.597,103.908 78.999,105.31 STD2.A
NetR11_2: R11.2 STD.K | length 6.8
  Bottom Layer w0.5: STD.K 118.237,45.339 119.888,46.99 119.888,48.813 R11.2
NetR15_1: R15.1 U4.26 | length 6.2
  Top Layer w0.2: R15.1 104.777,102.268 106.715,100.33 107.569,100.33 108.315,99.584 U4.26
RESET: B1.3 C6.2 Q1.3 R1.1 U1.3 | length 63.6
  Top Layer w0.2: v1(121.158,106.934) 122.809,105.283 v1(122.809,83.566)
  Bottom Layer w0.2: C6.2 117.68,110.412 v1(121.158,106.934) ; U1.3 120.493,81.25 v1(122.809,83.566)
  Bottom Layer w0.5: Q1.3 114.95,65.532 118.745,65.532 120.493,67.28 U1.3 ; C6.2 R1.1 117.704,113.955 B1.3
RI: U2.2
RTS: Q1.2 R5.1 U2.24 | length 13.5
  Top Layer w0.2: v1(107.315,63.754) 109.601,61.468 v1(109.601,59.055)
  Bottom Layer w0.2: U2.24 107.627,55.753 108.839,55.753 109.601,56.515 v1(109.601,59.055)
  Bottom Layer w0.5: R5.1 108.331,64.008 108.839,63.5 109.967,63.5 Q1.2
RX_0: R2.1 STD1.K U1.34 | length 92.9
  Top Layer w0.2: STD1.K 80.899,102.462 81.449,103.012 81.549,103.012 86.233,107.696 110.744,107.696 115.697,102.743 v1(115.697,99.187) ; v1(112.522,56.642) 118.999,63.119 118.999,84.074 117.953,85.12 v1(117.953,86.574) 117.953,95.474 119.888,97.409 v1(119.888,98.425)
  Bottom Layer w0.2: v1(115.697,99.187) 119.126,99.187 v1(119.888,98.425)
TX_0: STD2.K U1.35 U2.25 | length 100.9
  Top Layer w0.2: STD2.K 80.899,105.51 84.355,108.966 111.379,108.966 116.84,103.505 v1(116.84,100.457) ; v1(110.617,55.753) 113.411,55.753 119.888,62.23 119.888,84.582 119.223,85.247 v1(119.223,86.574) 119.223,95.22 121.158,97.155 v1(121.158,99.314)
  Bottom Layer w0.2: U2.25 109.093,55.245 109.601,55.753 v1(110.617,55.753) ; v1(116.84,100.457) 120.015,100.457 v1(121.158,99.314)
pads on no net: B1. B1.1 B1.4 B2. B2.1 B2.4 B3.1 B3.3 B4.1 B4.3 B5.1 B5.3 B6.1 B6.3 B7.1 B7.3 D1.2 IC1.1 J1. J1.A8 J1.B4_A9 J1.B8 SW1. SW1.EP U1.4 U1.5 U1.17 U1.18 U1.19 U1.20 U1.21 U1.22 U1.32 U1.40_1 U1.40_2 U1.40_3 U1.40_4 U1.40_5 U1.40_6 U1.40_7 U1.40_8 U1.40_9 U1.40_10 U1.40_11 U1.40_12 U2.9 U2.10 U2.12 U2.13 U2.14 U2.15 U2.16 U2.17 U2.18 U2.19 U2.20 U2.21 U2.22 U5.7 U6.7 U7.7 U8. U8.1 U8.8 U8.9 U8.10

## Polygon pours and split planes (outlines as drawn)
GND on Top Layer "Top Layer-No Net" (solid, pour order 0): 76.835,44.196 ccw(c81.47,44.133) 81.407,39.497 119.888,39.497 ccw(c119.951,44.132) 124.587,44.069 124.587,122.301 ccw(c119.952,122.364) 120.015,127 81.534,127 ccw(c81.471,122.365) 76.835,122.428
GND on Bottom Layer "Top Layer-No Net1" (solid, pour order 1): 76.835,44.196 ccw(c81.47,44.133) 81.407,39.497 119.888,39.497 ccw(c119.951,44.132) 124.587,44.069 124.587,122.301 ccw(c119.952,122.364) 120.015,127 81.534,127 ccw(c81.471,122.365) 76.835,122.428

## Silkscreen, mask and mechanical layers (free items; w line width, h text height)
Top Overlay:
  drawing of 3241 lines, arcs and shapes, not listed
  text "nRF-BOX" at 87.757,114.554 h3
  text "Tx" at 81.693,104.442 h1.6
  text "Rx" at 81.693,101.394 h1.6
  text "x CiferTech x" at 94.742,88.773 h1
  text "X" at 112.903,72.263 h3.5 r270
  text "X" at 85.725,57.785 h2 r90
  text "X" at 92.202,47.498 h4 r90
Bottom Overlay:
  drawing of 762 lines, arcs and shapes, not listed
  text "CiferTech" at 109.976,107.349 h0.67
Mechanical 1:
  circle w0.208: c121.031,42.672 r1.5
  circle w0.208: c122.047,121.285 r1.5
  circle w0.208: c80.391,42.799 r1.5
  circle w0.208: c79.375,121.412 r1.5
  lines w0.1: 76.835,44.196 ccw(c81.47,44.133) 81.407,39.497 119.888,39.497 ccw(c119.951,44.132) 124.587,44.069 124.587,122.301 ccw(c119.952,122.364) 120.015,127 81.534,127 ccw(c81.471,122.365) 76.835,122.428 76.835,44.196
